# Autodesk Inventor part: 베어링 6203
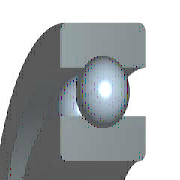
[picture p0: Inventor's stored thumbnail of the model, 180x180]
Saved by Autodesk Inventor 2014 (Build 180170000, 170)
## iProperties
IsCustomPart: 0
Company: 한국ATC센터
Created: 2014-10
Part Number: 베어링 6203
Material: 강철
Description: 깊은 그루브 볼 베어링
Document SubType Name: Modeling
Standard: KS B 2023
Designer: KYOUNG IL JANG
Standards Organization: KS
Language: ko-KR
Size Designation: 6203 - 17 x 40 x 12
Categories: <MemberInstance><Categories><Category DisplayName="샤프트 부품" InternalName="7f7aeb1f-a693-4053-b835-cee3144e0d98" Mnemonic="SHFT"><Category DisplayName="베어링" Inter
Density: 7.85 g/cm^3
Mass: 64.8982 g
Surface Area: 64.3582 cm^2
Volume: 8.26729 cm^3
Appearance: 강철 - 광택
Author: KYOUNG IL JANG
Revision Number: 1
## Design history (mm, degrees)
sketch "스케치" dims "d0" = 5.98 (= -0.26 x WD + 0.26 x BD)
  geometry: L1 (3.01, 14.25)-(8.99, 14.25); L2 (6, 14.25)-(6, 11.26); L3 (6, 14.25)-(6, 17.24); L4 (3.778, 12.249)-(0, 12.249); L5 (0, 8.5)-(12, 8.5); L6 (3.778, 16.251)-(0, 16.251); L7 (0, 20)-(12, 20); L8 (12, 8.5)-(12, 12.249); L9 (8.222, 12.249)-(12, 12.249); L10 (8.222, 16.251)-(12, 16.251); L11 (12, 20)-(12, 16.251); L12 (-1.4, 0)-(8.4, 0) reference; L13 (0, -0.3)-(0, 5.3) reference
  constraints: 22 end point, 4 point on line, 2 collinear, 2 perpendicular, 2 symmetric about line, 1 midpoint, 1 parallel, 14 other
  dimensions: "d9" = 17 diameter of L5 L12 (= WD); "d11" = 40 diameter of L7 L12 (= BD); "d12" = 12 distance between parallel lines of L8 L13 (= KB); "d13" = 24.498 diameter of L9 L12 (= 0.326 x BD + 0.674 x WD)
revolve "본체" stored, may be unused: angle "d6" = 90 deg
revolve "볼" stored, may be unused: angle "d7" = 90 deg
pattern_circular "IDS_ARRAYBALL[SIMPL:T]" dims angle "d3" = 360 deg
body "Solid1"
fillet "모깎기1" dims "d1" = 0.6 (= KRS)
other parameters: "WD" = 17 [user parameter; used in 5 equation terms], "BD" = 40 [user parameter; used in 5 equation terms], "KB" = 12 [user parameter; used in 1 equation term], "KRS" = 0.6 [user parameter; used in 1 equation term], "d4" = 0, "d5" = 0, "d8" = 0, "d14" = 0, "d15" = 0, "BBA" = 0 [user parameter], "BC0" = 4750000 [user parameter], "BC" = 9560000 [user parameter], "WR" = 8.5 (= 0.5 x WD) [user parameter]
